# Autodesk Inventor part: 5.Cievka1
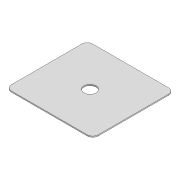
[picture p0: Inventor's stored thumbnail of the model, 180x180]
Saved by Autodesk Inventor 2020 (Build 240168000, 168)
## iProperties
Created: 2022-04
Part Number: 5.Cievka1
Material: Generic
Document SubType Name: Modeling
Designer: marti
Density: 1 g/cm^3
Appearance: Default
Author: marti
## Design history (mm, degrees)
sketch "Sketch1"
  geometry: L1 (16, 15)-(-16, 15); L2 (-16, 15)-(-16, -15); L3 (-16, -15)-(16, -15); L4 (16, -15)-(16, 15); L5 (16, 15)-(-16, -15); L6 (-16, 15)-(16, -15); 1 further point
  constraints: 12 end point, 2 midpoint, 2 parallel, 1 horizontal, 1 perpendicular
  dimensions: "d0" = 32 distance of L3.end L2.end; "d1" = 30 distance of L2.end L1.end
extrude "Extrusion1" new body sketch "Sketch1" distance "d2" = 0.4; taper "d3" = 0 deg
sketch "Sketch2"
  geometry: C1 r 2.25 at (0, 0); 1 further point
  constraints: 1 centre point, 1 coincident
  dimensions: "d4" = 4.5 diameter of C1
extrude "Extrusion2" cut sketch "Sketch2" distance "d5" = 0.4; taper "d6" = 0 deg
fillet "Fillet1" dims "d7" = 2
body "Solid1"
